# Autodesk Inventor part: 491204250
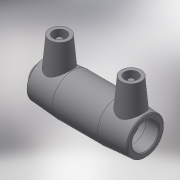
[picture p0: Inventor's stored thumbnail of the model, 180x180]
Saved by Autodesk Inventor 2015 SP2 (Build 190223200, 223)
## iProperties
Created: 2017-06
Part Number: 491204250
Material: Generic
Description: PLASSON END CAP 250
Document SubType Name: Modeling
Designer: KIM
Mass: 38.9236 g
Surface Area: 152.394 cm^2
Volume: 38.9236 cm^3
Density: 1 g/cm^3
Appearance: Default
Author: KIM
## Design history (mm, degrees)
derived "491204.ipt"
feature "Solid1::491204.ipt"
tag "TaggingFeature1"
body "Solid1"
other parameters: "d0" = 251, "d2" = 311, "d3" = 123, "d4" = 86, "d5" = 279.9, "d6" = 237.5, "d8" = 168 deg, "d10" = 49.2, "d11" = 16.4, "d13" = 275.2, "d14" = 17.6296, "d15" = 123, "d16" = 123, "d17" = 237.5, "d19" = 3.52592, "d20" = 168 deg, "d22" = 292.34, "d23" = 311, "d24" = 283.5698, "d25" = 135 deg, "d26" = 123.84, "d27" = 135 deg, "d29" = 156, "d30" = 15, "d31" = 110.08, "d34" = 5 deg, "d35" = 15, "d39" = 5 deg, "d41" = 4, "d42" = 14, "d43" = 0, "d45" = 4, "d46" = 14, "d47" = 0, "d48" = 344, "d49" = 1, "d52" = 6.192, "d53" = 275, "d54" = 6.192, "d56" = 25, "d57" = 7.5, "d60" = 51.6, "d61" = 5, "d63" = 344, "d64" = 1, "d68" = 275, "d69" = 6.88, "d70" = 0, "d71" = 6.192, "d72" = 3, "d73" = 0, "d74" = 35.67, "d75" = 11.89, "d76" = 3, "d77" = 0, "L_" = 344, "L_1" = 123, "D_" = 311, "A_" = 156, "d_2" = 12, "L_0" = 251, "d55" = 25
